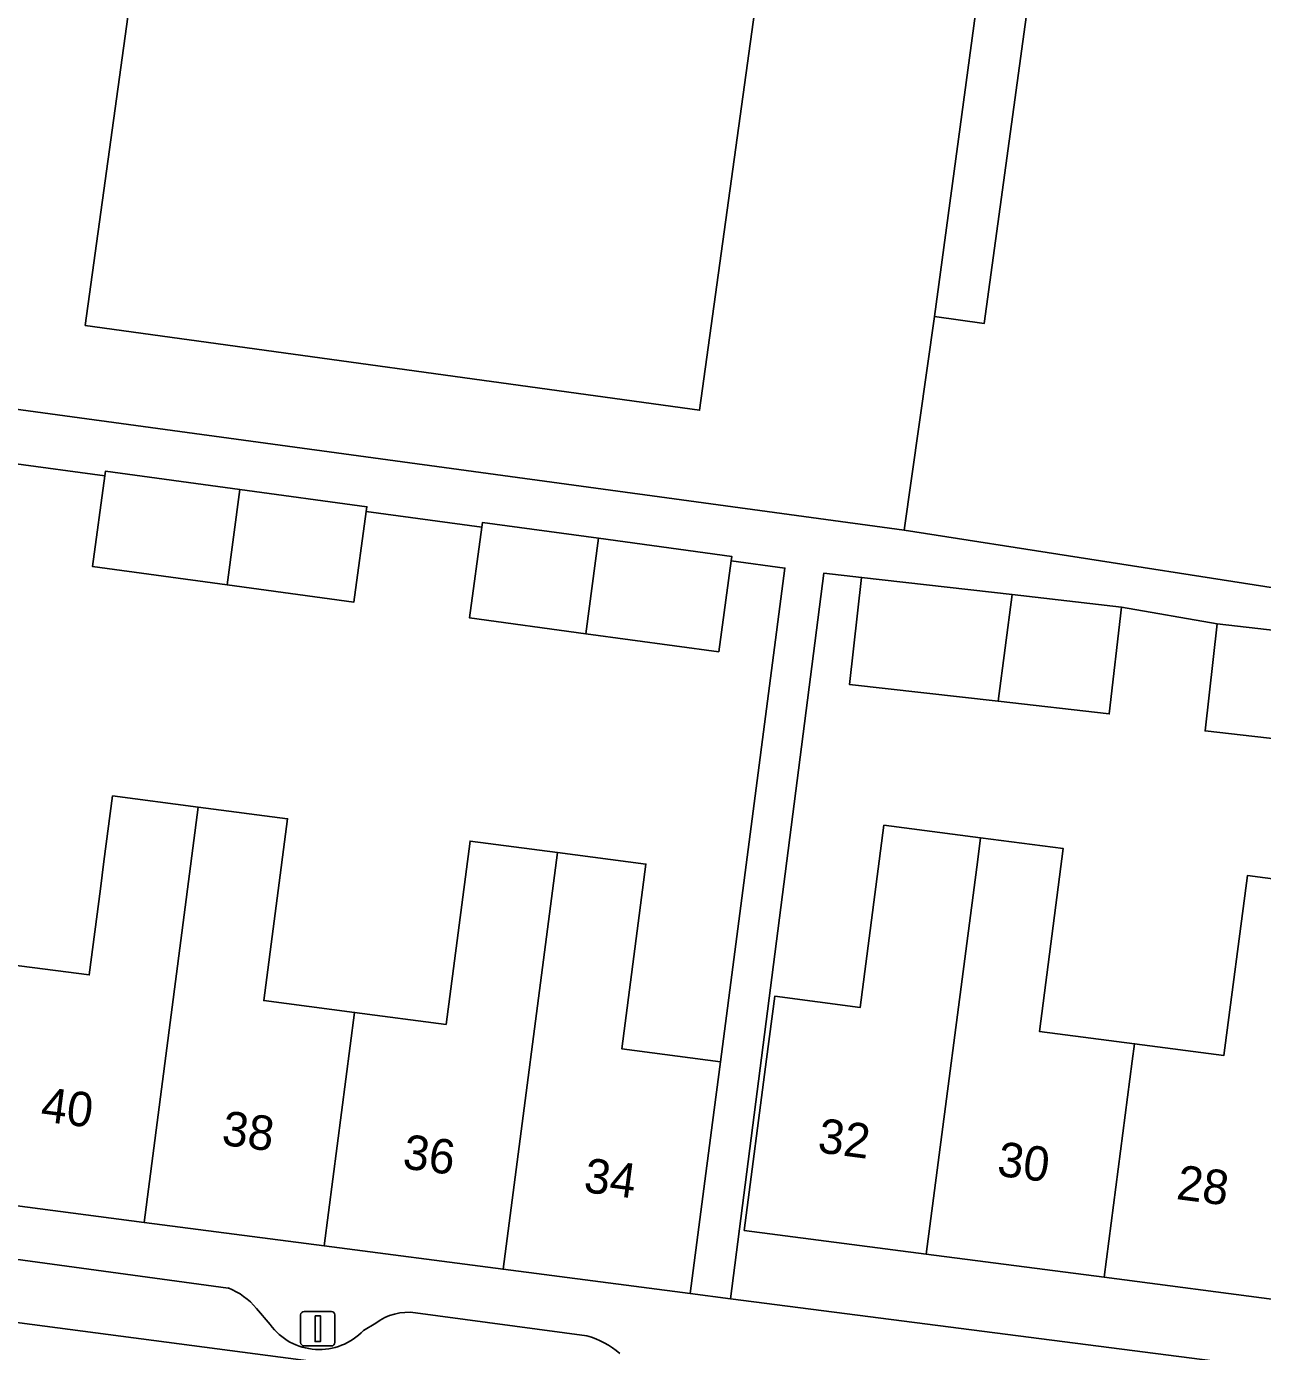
# Model space of a CAD drawing. Extents: x 161838 to 162344, y 381620 to 382160.
# Drawn here: x 161936.08 to 161971.89, y 381708.64 to 381747.04 of the extents above; entities that cross this region are included whole.
import ezdxf

# ---------------------------------------------------------------- set-up
doc = ezdxf.new("R2010")
doc.units = 0
for name, color, linetype in [('IMGEO_Erf', 7, 'Continuous'), ('IMGEO_Lichtmast', 7, 'Continuous'), ('IMGEO_Pand', 7, 'Continuous'), ('IMGEO_Pand_nummerreeks', 7, 'Continuous'), ('IMGEO_Pand_overbouw', 7, 'Continuous'), ('IMGEO_Pand_vergunning_verleend', 7, 'Continuous'), ('IMGEO_Parkeervlak_open', 7, 'Continuous'), ('IMGEO_Rijbaan_lokaal_open', 7, 'Continuous'), ('IMGEO_Voetpad_open', 7, 'Continuous')]:
    doc.layers.add(name, color=color, linetype=linetype)

msp = doc.modelspace()

# ---------------------------------------------------------------- linework, layer by layer
at = {"layer": 'IMGEO_Erf'}
for points in [[(161963.918, 381750), (161962.379, 381738.634), (161961.501, 381732.448), (161991.926, 381727.689), (161972.452, 381733.08), (161977.428, 381751.055)], [(161935.255, 381719.901), (161937.893, 381719.556), (161938.219, 381722.055), (161938.321, 381722.84), (161938.57, 381724.745), (161941.055, 381724.421), (161943.64, 381724.083), (161942.952, 381718.812), (161945.583, 381718.469), (161948.235, 381718.123), (161948.928, 381723.435), (161951.457, 381723.105), (161954.02, 381722.771), (161953.322, 381717.417), (161956.184, 381717.043), (161958.051, 381731.346), (161956.49, 381731.558), (161956.131, 381728.922), (161952.284, 381729.446), (161948.913, 381729.905), (161949.272, 381732.537), (161945.92, 381732.992), (161945.561, 381730.361), (161941.894, 381730.86), (161937.991, 381731.391), (161938.349, 381734.019), (161935.636, 381734.387)], [(161974.539, 381726.139), (161970.224, 381726.63), (161970.576, 381729.729), (161967.797, 381730.219), (161967.444, 381727.121), (161964.232, 381727.486), (161959.918, 381727.977), (161960.27, 381731.076), (161959.177, 381731.202), (161956.476, 381710.172), (161987.777, 381706.147)], [(161972.448, 381710.122), (161967.295, 381710.794), (161962.142, 381711.466), (161956.87, 381712.153), (161957.517, 381717.112), (161957.755, 381718.938), (161960.23, 381718.615), (161960.918, 381723.895), (161963.716, 381723.53), (161966.113, 381723.218), (161965.422, 381717.92), (161968.178, 381717.561), (161970.769, 381717.223), (161971.448, 381722.434), (161974.011, 381722.1)]]:
    msp.add_lwpolyline(points, dxfattribs=at)
at = {"layer": 'IMGEO_Lichtmast'}
for p, q in [((161944.12, 381709.805), (161944.91, 381709.805)), ((161944.91, 381709.805), (161944.12, 381709.805)), ((161944.02, 381708.905), (161944.02, 381709.705)), ((161944.02, 381709.705), (161944.02, 381708.905)), ((161945.01, 381709.705), (161945.01, 381708.905)), ((161945.01, 381708.905), (161945.01, 381709.705)), ((161944.91, 381708.805), (161944.12, 381708.805)), ((161944.12, 381708.805), (161944.91, 381708.805))]:
    msp.add_line(p, q, dxfattribs=at)
msp.add_lwpolyline([(161944.44, 381709.68), (161944.59, 381709.68), (161944.59, 381708.93), (161944.44, 381708.93), (161944.44, 381709.68)], dxfattribs=at)
for centre, start, end in [((161944.12, 381709.705), 90, 180), ((161944.12, 381709.705), 90, 180), ((161944.91, 381709.705), 0, 90), ((161944.91, 381709.705), 360, 90), ((161944.12, 381708.905), 180, 270), ((161944.12, 381708.905), 180, 270), ((161944.91, 381708.905), 270, 0), ((161944.91, 381708.905), 270, 0)]:
    msp.add_arc(centre, 0.1, start, end, dxfattribs=at)
at = {"layer": 'IMGEO_Pand'}
for points in [[(161943.773, 381771.406), (161941.27, 381771.689), (161940.656, 381766.246), (161939.055, 381754.703), (161940.747, 381754.512), (161940.179, 381750), (161940.003, 381748.598), (161932.761, 381749.584), (161928.68, 381736.917), (161933.635, 381736.242), (161961.501, 381732.448), (161962.379, 381738.634), (161963.918, 381750), (161965.98, 381765.232), (161966.661, 381770.185), (161958.302, 381771.128), (161958.15, 381769.783)], [(161942.255, 381733.628), (161938.368, 381734.158), (161938.349, 381734.019), (161937.991, 381731.391), (161941.894, 381730.86)], [(161945.92, 381732.992), (161945.938, 381733.127), (161942.255, 381733.628), (161941.894, 381730.86), (161945.561, 381730.361)], [(161952.644, 381732.214), (161949.29, 381732.67), (161949.272, 381732.537), (161948.913, 381729.905), (161952.284, 381729.446)], [(161956.49, 381731.558), (161956.508, 381731.688), (161952.644, 381732.214), (161952.284, 381729.446), (161956.131, 381728.922)], [(161964.232, 381727.486), (161964.636, 381730.579), (161960.27, 381731.076), (161959.918, 381727.977)], [(161964.232, 381727.486), (161967.444, 381727.121), (161967.797, 381730.219), (161964.636, 381730.579)], [(161974.539, 381726.139), (161974.942, 381729.232), (161970.576, 381729.729), (161970.224, 381726.63)], [(161941.055, 381724.421), (161938.57, 381724.745), (161938.321, 381722.84), (161938.219, 381722.055), (161937.893, 381719.556), (161935.255, 381719.901), (161934.405, 381713.048), (161939.487, 381712.385)], [(161941.055, 381724.421), (161939.487, 381712.385), (161944.702, 381711.705), (161945.583, 381718.469), (161942.952, 381718.812), (161943.64, 381724.083)], [(161962.142, 381711.466), (161963.634, 381722.9), (161963.716, 381723.53), (161960.918, 381723.895), (161960.23, 381718.615), (161957.755, 381718.938), (161957.517, 381717.112), (161956.87, 381712.153)], [(161951.457, 381723.105), (161948.928, 381723.435), (161948.235, 381718.123), (161945.583, 381718.469), (161944.702, 381711.705), (161949.883, 381711.029)], [(161967.295, 381710.794), (161968.113, 381717.061), (161968.178, 381717.561), (161965.422, 381717.92), (161966.113, 381723.218), (161963.716, 381723.53), (161963.634, 381722.9), (161962.142, 381711.466)], [(161951.457, 381723.105), (161949.883, 381711.029), (161955.308, 381710.322), (161955.954, 381715.281), (161956.184, 381717.043), (161953.322, 381717.417), (161954.02, 381722.771)], [(161967.295, 381710.794), (161972.448, 381710.122), (161973.94, 381721.553), (161974.011, 381722.1), (161971.448, 381722.434), (161970.769, 381717.223), (161968.178, 381717.561), (161968.113, 381717.061)]]:
    msp.add_lwpolyline(points, close=True, dxfattribs=at)
at = {"layer": 'IMGEO_Pand_overbouw'}
msp.add_lwpolyline([(161943.773, 381771.406), (161958.15, 381769.783), (161958.302, 381771.128), (161966.661, 381770.185), (161965.98, 381765.232), (161963.918, 381750), (161962.379, 381738.634), (161963.825, 381738.437), (161965.405, 381750), (161968.184, 381770.345), (161944.022, 381773.611)], close=True, dxfattribs=at)
at = {"layer": 'IMGEO_Pand_vergunning_verleend'}
msp.add_lwpolyline([(161937.774, 381738.382), (161942.776, 381774.585), (161967.825, 381771.125), (161966.144, 381758.957), (161958.899, 381759.958), (161955.579, 381735.923)], close=True, dxfattribs=at)
at = {"layer": 'IMGEO_Parkeervlak_open'}
for points in [[(161941.923, 381710.484), (161932.56, 381711.759)], [(161928.816, 381710.405), (161954.008, 381707.086), (161955.333, 381706.911)], [(161943.135, 381709.425), (161942.739, 381709.893)], [(161952.314, 381709.102), (161947.347, 381709.769)], [(161946.194, 381709.47), (161945.84, 381709.252)]]:
    msp.add_lwpolyline(points, dxfattribs=at)
for centre, radius, start, end in [((161941.176, 381708.594), 2.033, 39.7366, 68.4344), ((161947.15, 381708.157), 1.624, 83.0238, 126.052), ((161944.559, 381710.463), 1.762, 216.0755, 316.6057), ((161951.501, 381706.447), 2.776, 50.4468, 72.9731)]:
    msp.add_arc(centre, radius, start, end, dxfattribs=at)
at = {"layer": 'IMGEO_Rijbaan_lokaal_open'}
msp.add_lwpolyline([(161954.008, 381707.086), (161928.816, 381710.405), (161928.688, 381710.422), (161928.47, 381708.756), (161928.26, 381707.154), (161928.51, 381707.121), (161953.57, 381703.801)], close=True, dxfattribs=at)
at = {"layer": 'IMGEO_Voetpad_open'}
for points in [[(161991.926, 381727.689), (161961.501, 381732.448), (161933.635, 381736.242)], [(161935.636, 381734.387), (161938.349, 381734.019), (161938.368, 381734.158), (161942.255, 381733.628), (161945.938, 381733.127), (161945.92, 381732.992), (161949.272, 381732.537), (161949.29, 381732.67), (161952.644, 381732.214), (161956.508, 381731.688), (161956.49, 381731.558), (161958.051, 381731.346), (161956.184, 381717.043), (161955.954, 381715.281), (161955.308, 381710.322), (161956.476, 381710.172), (161959.177, 381731.202), (161960.27, 381731.076), (161964.636, 381730.579), (161967.797, 381730.219), (161970.576, 381729.729), (161974.942, 381729.232)], [(162052.602, 381697.712), (162049.351, 381697.959), (162041.781, 381698.968), (162035.43, 381699.815), (162034.419, 381699.947), (162028.849, 381700.688), (162023.552, 381701.393), (162018.578, 381702.055), (162009.676, 381703.239), (162004.764, 381703.893), (162000, 381704.527), (161999.589, 381704.582), (161994.25, 381705.292), (161989.039, 381705.985), (161987.777, 381706.147), (161956.476, 381710.172), (161955.308, 381710.322), (161949.883, 381711.029), (161944.702, 381711.705), (161939.487, 381712.385), (161934.405, 381713.048)], [(161932.56, 381711.759), (161941.923, 381710.484)], [(161942.739, 381709.893), (161943.135, 381709.425)], [(161947.347, 381709.769), (161952.314, 381709.102)], [(161945.84, 381709.252), (161946.194, 381709.47)]]:
    msp.add_lwpolyline(points, dxfattribs=at)
for centre, radius, start, end in [((161941.176, 381708.594), 2.033, 39.7366, 68.4344), ((161947.15, 381708.157), 1.624, 83.0238, 126.052), ((161944.559, 381710.463), 1.762, 216.0755, 316.6057), ((161951.501, 381706.447), 2.776, 50.4468, 72.9731)]:
    msp.add_arc(centre, radius, start, end, dxfattribs=at)

# ---------------------------------------------------------------- texts
at = {"layer": 'IMGEO_Pand_nummerreeks'}
for s, rotation, p in [('40', 352.5687, (161936.459, 381715.321)), ('38', 352.5707, (161941.704, 381714.637)), ('32', 352.5703, (161958.97, 381714.42)), ('36', 352.5707, (161946.947, 381713.954)), ('30', 352.5703, (161964.169, 381713.742)), ('34', 352.5707, (161952.192, 381713.27)), ('28', 352.5703, (161969.362, 381713.065))]:
    msp.add_text(s, height=1, rotation=rotation, dxfattribs=at).set_placement(p)

doc.saveas('drawing.dxf')
